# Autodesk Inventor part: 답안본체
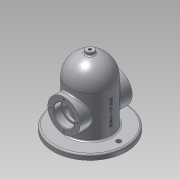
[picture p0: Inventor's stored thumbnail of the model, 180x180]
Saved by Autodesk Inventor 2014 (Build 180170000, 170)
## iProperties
Created: 2019-11
Part Number: 답안본체
Material: 알루미늄 6061
Document SubType Name: Modeling
Designer: net
Density: 2.71 g/cm^3
Appearance: 알루미늄 - 평지
Mass: 1110.22 g
Surface Area: 883.263 cm^2
Volume: 409.676 cm^3
Author: net
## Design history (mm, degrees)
sketch "스케치1"
  geometry: C1 r 40 at (0, 0); 1 further point
  constraints: 1 centre point, 1 coincident
  dimensions: "d0" = 80 diameter of C1
extrude "돌출1" new body sketch "스케치1" distance "d1" = 90; taper "d2" = 0 deg
sketch "스케치2"
  geometry: L1 (40, 90)-(-40, 90) reference; L2 (0, 90)-(0, 130); A1 r 40 centre (0, 90) between (0, 130) and (-40, 90); 1 further point
  constraints: 2 end point, 2 point on circle, 1 centre point, 1 midpoint, 1 perpendicular
  dimensions: "d3" = 40 distance of L2.start L2.end; "d4" = 40 radius of A1
revolve "회전1" sketch "스케치2" stored, may be unused: angle "d5" = 90 deg
sketch "스케치4"
  geometry: L1 (40, 90)-(-40, 90) reference; L2 (0, 90)-(0, 120); A1 r 30 centre (0, 90) between (0, 120) and (-30, 90); 1 further point
  constraints: 2 end point, 2 point on circle, 1 centre point, 1 coincident, 1 midpoint, 1 point on line, 1 vertical
  dimensions: "d9" = 30 distance of L2.start L2.end; "d10" = 30 radius of A1
revolve "회전2" sketch "스케치4" stored, may be unused: angle "d11" = 90 deg
sketch "스케치6"
  geometry: C1 r 31 at (0, 50); 1 further point
  constraints: 1 centre point, 1 vertical alignment
  dimensions: "d12" = 50 distance of point (0, 0) C1.centre; "d13" = 62 diameter of C1
extrude "돌출3" join sketch "스케치6" distance "d14" = 50; taper "d16" = 0 deg; dims "d15" = 50, "d17" = 0
sketch "스케치7"
  geometry: C1 r 40 at (0, 0) reference; C2 r 30 at (0, 0)
  constraints: 1 centre point, 1 coincident
  dimensions: "d18" = 60 diameter of C2
extrude "돌출4" cut sketch "스케치7" distance "d19" = 90; taper "d20" = 0 deg
sketch "스케치8"
  geometry: C1 r 31 at (0, 0) reference; C2 r 20 at (0, 0); 1 further point
  constraints: 1 centre point, 1 coincident
  dimensions: "d21" = 40 diameter of C2
extrude "돌출5" cut sketch "스케치8" distance "d22" = 15; taper "d23" = 0 deg
sketch "스케치9"
  geometry: C1 r 31 at (0, 0) reference; C2 r 20 at (0, 0); 1 further point
  constraints: 1 centre point, 1 coincident
  dimensions: "d24" = 40 diameter of C2
extrude "돌출6" cut sketch "스케치9" distance "d25" = 15; taper "d26" = 0 deg
sketch "스케치10"
  geometry: C1 r 20 at (0, 0) reference; C2 r 16.5 at (0, 0); 1 further point
  constraints: 1 centre point, 1 coincident
  dimensions: "d27" = 33 diameter of C2
extrude "돌출7" cut sketch "스케치10" distance "d28" = 90; taper "d29" = 0 deg
sketch "스케치11"
  geometry: C1 r 40 at (0, 0) reference; C2 r 70 at (0, 0); 1 further point
  constraints: 1 centre point, 1 coincident
  dimensions: "d30" = 140 diameter of C2
extrude "돌출8" join sketch "스케치11" distance "d31" = 10; taper "d32" = 0 deg
sketch "스케치12"
  geometry: C1 r 20 at (0, 0) reference; 2 further points
  constraints: 1 vertical alignment
  dimensions: "d33" = 26 distance of point (0, 26) C1.centre
hole "구멍1" sketch "스케치12" at (0, 26) diameter "d34" = 3.242; stored, may be unused: countersink angle "d38" = 90 deg, drill point angle "d40" = 118 deg; dims "d35" = 8, "d36" = 4, "d37" = 2, "d39" = 10
node "작업 평면1"
sketch "스케치13"
  geometry: C1 r 7.5 at (0, 0); 1 further point
  constraints: 1 centre point, 1 coincident
  dimensions: "d45" = 15 diameter of C1
extrude "돌출9" join sketch "스케치13" stored distance "d46" = 10; taper "d47" = 0 deg
hole "구멍2" diameter "d50" = 5.188; stored, may be unused: countersink angle "d54" = 90 deg, drill point angle "d56" = 118 deg; dims "d48" = 10, "d49" = 10, "d51" = 20, "d52" = 4, "d53" = 2, "d55" = 20
sketch "스케치14"
  geometry: C1 r 40 at (0, 0) reference; 2 further points
  constraints: 2 horizontal alignment
  dimensions: "d57" = 55 distance of C1.centre point (55, 0); "d58" = 55 distance of point (-55, 0) C1.centre
hole "구멍3" sketch "스케치14" at (55, 0), (-55, 0) diameter "d59" = 9; stored, may be unused: countersink angle "d63" = 90 deg, drill point angle "d65" = 118 deg; dims "d60" = 20, "d61" = 4, "d62" = 2, "d64" = 20
node "작업 평면2"
sketch "스케치15"
  geometry: L1 (-70, 0)-(70, 0) reference; 3 further points
  constraints: 1 midpoint, 1 vertical alignment, 1 other
  dimensions: "d67" = 50 distance from line of point (0, 50) L1
feature "엠보싱1" sketch "스케치15" dims "d16" = 0, "d68" = 0.5, "d69" = 0
fillet "모깎기1" dims "d70" = 3
fillet "모깎기2" dims "d71" = 3
chamfer "모따기1" distance "d72" = 1; stored, may be unused: second distance "d73" = 2, angle "d74" = 45 deg
fillet "모깎기3" dims "d75" = 0.3
node "솔리드1"
pattern_circular "원형 패턴1" dims angle "d42" = 360 deg
mirror "대칭1"
other parameters: "d44" = 135
